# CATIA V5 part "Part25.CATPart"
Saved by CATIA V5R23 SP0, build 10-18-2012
Part number: Part2
Bounding box of the stored display mesh (mm): x 0 to 1, y 0 to 16, z 0 to 50
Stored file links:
  G:\STOIXEIO_SINDESIS\Part25.CATPart
  C:\Documents and Settings\ZYGOMALAS\Desktop\STOIXEIO SYNDESHS.CATPart
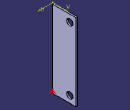
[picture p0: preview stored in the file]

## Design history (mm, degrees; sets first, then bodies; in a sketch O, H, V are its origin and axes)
Sketch1 on yz-plane, origin (0, 0, 0), H (0, 1, 0), V (0, 0, 1)
  line L1 (0, 0) -> (16, 0)
  line L2 (16, 0) -> (16, 50)
  line L3 (16, 50) -> (0, 50)
  line L4 (0, 50) -> (0, 0)
  circle A1 centre (12, 45.5) radius 2.1
  circle A2 centre (12, 4.5) radius 2.1
  horizontal: L1 H, L3 H
  vertical: L2 V, L4 V
WSupportSet1: ActiveGrid {3dwsupport RefPoint {point stored without definition}, 3DWOS ({wsupport Support xy-plane, RefPoint {3dwsupport}, GridIn {cartgrid Value 100, Stepbid1 0, Value 100, Stepbid2 0, Direction (1, 0, 0)}, GeometricData ({line type PtDir, Direction (1, 0, 0), Support xy-plane}; {line type PtDir, Direction (0, 1, 0), Support yz-plane})}; {wsupport Support yz-plane, RefPoint {3dwsupport}, GridIn {cartgrid Value 100, Stepbid1 0, Value 100, Stepbid2 0, Direction (0, 1, 0)}, GeometricData ({line type PtDir, Direction (0, 1, 0), Support yz-plane}; {line type PtDir, Direction (0, 0, 1), Support zx-plane})}; {wsupport Support zx-plane, RefPoint {3dwsupport}, GridIn {cartgrid Value 100, Stepbid1 0, Value 100, Stepbid2 0, Direction (0, 0, 1)}, GeometricData ({line type PtDir, Direction (0, 0, 1), Support zx-plane}; {line type PtDir, Direction (1, 0, 0), Support xy-plane})}), GeometricData ({line type PtDir, RefPoint {point stored without definition}, Direction (1, 0, 0), Support xy-plane}; {line type PtDir, RefPoint {point stored without definition}, Direction (0, 1, 0), Support yz-plane}; {line type PtDir, RefPoint {point stored without definition}, Direction (0, 0, 1), Support zx-plane})}
AxisSystem1: origin (0, 0, 0), X (1, 0, 0), Y (0, 1, 0), Z (0, 0, 1)
Body1 (main body)
  Pad1: profile Sketch1, direction (1, 0, 0), length 1
  Sketch2 on face of Pad1, origin (0, 0, 50), H (1, 0, 0), V (0, 1, 0)
  Sketch3 on xy-plane, origin (0, 0, 0), H (1, 0, 0), V (0, 1, 0)
    circle A1 centre (0.5, 0) radius 1
  Pocket1: profile Sketch3, direction (0, 0, 1), length 50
